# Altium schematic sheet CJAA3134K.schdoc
size 127 x 101 mm
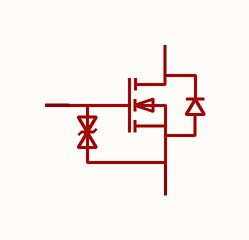
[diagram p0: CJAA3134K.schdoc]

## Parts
Q?  cjaa3134k  [WBFBP-03E_L1.0-W0.6-P0.64-BL]  (value not drawn)

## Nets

Not connected (* = marked no-connect by the designer): Q? 1(G) 2(S) 3(D)

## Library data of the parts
Q? = cjaa3134k: 数量:1个N沟道;漏源电压(Vdss):20V;连续漏极电流(Id):750mA;导通电阻(RDS(on)):800mΩ@1.8V;耗散功率(Pd):100mW;阈值电压(Vgs(th)):350mV;; Manufacturer: CJ(江苏长电/长晶); AddInBom: yes; ModelId: 072dcf228994456dbe83693440270b5f; ModelTransform: 40.1574,23.622,0,0,0,0,-0.001,0,0; Number: 1个N沟道; Drain to Source Voltage: 20V; Current - Continuous Drain(Id): 750mA; Pd - Power Dissipation: 100mW; Gate Threshold Voltage (Vgs(th)): 350mV; Input Capacitance(Ciss): 120pF; Reverse Transfer Capacitance (Crss@Vds): 15pF; Type: N沟道; Output Capacitance(Coss): 20pF; Vgs: ±12V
